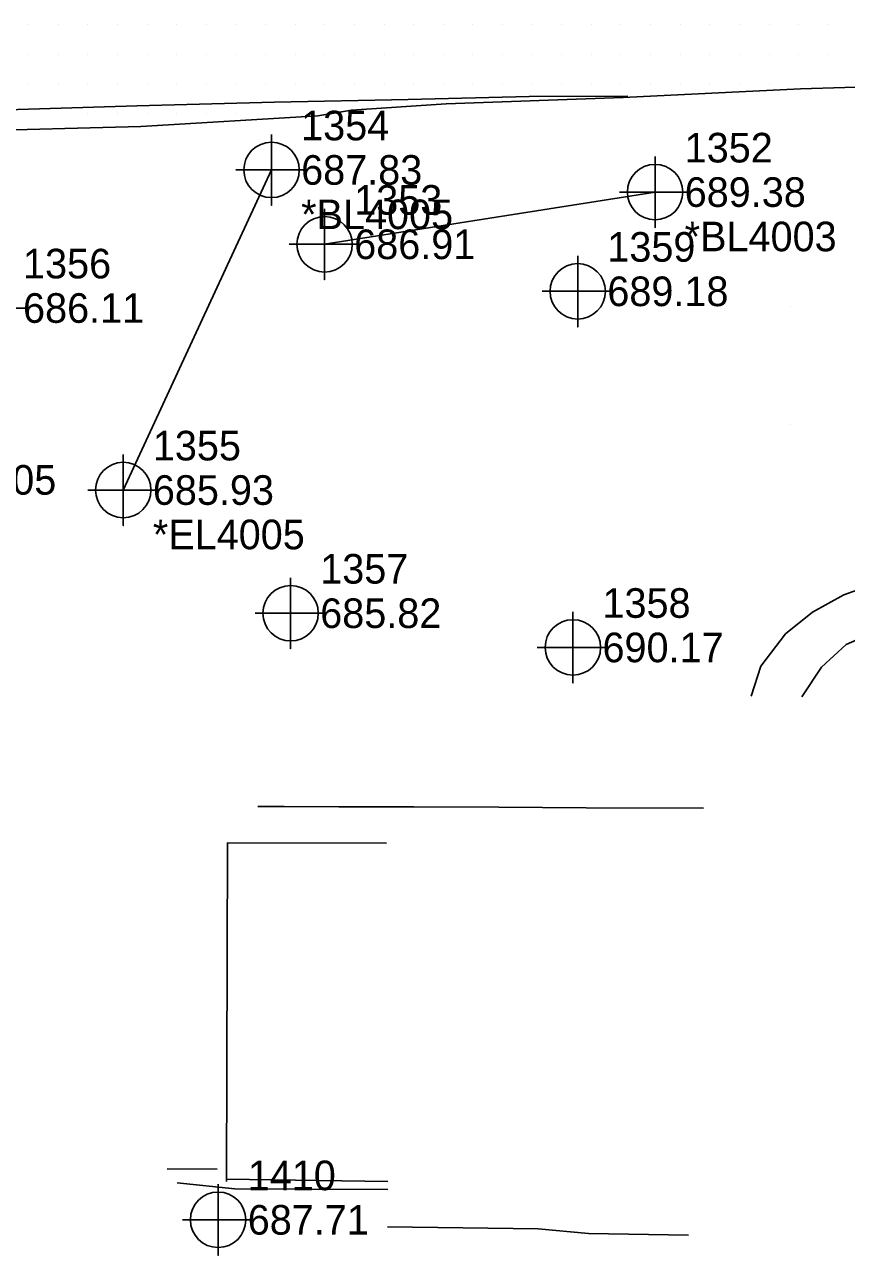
# Model space of a CAD drawing. Extents: x 1755643 to 1760494, y 736519 to 737621.
# Drawn here: x 1759120.9 to 1759190.3, y 736914.8 to 737018.8 of the extents above; entities that cross this region are included whole.
import ezdxf

# ---------------------------------------------------------------- set-up
doc = ezdxf.new("R2010")
doc.units = 0
for name, color, linetype in [('Exist Horizontal Alignment Curve and Spiral Data', 7, 'Continuous'), ('Exist Horizontal Alignment Direction Label', 7, 'Continuous'), ('Exist Railroads Standard Gauge', 7, 'Continuous'), ('Exist Roads EOT', 7, 'Continuous'), ('Old_Level_1', 7, 'Continuous'), ('Old_Level_10', 7, 'Continuous'), ('Old_Level_2', 7, 'Continuous'), ('Old_Level_3', 7, 'Continuous'), ('Prop Corridor Linear Feature', 7, 'Continuous'), ('Prop Dimension', 7, 'Continuous'), ('Prop EOT Dash', 7, 'Continuous'), ('Prop Horizontal Alignment Direction Label', 7, 'Continuous'), ('Prop Lane Lines', 7, 'Continuous'), ('Prop Paint Stripe', 7, 'Continuous'), ('Prop Paved Shoulder', 7, 'Continuous'), ('Scratch_Level_1', 7, 'Continuous'), ('Scratch_Level_2', 7, 'Continuous'), ('Scratch_Level_5', 7, 'Continuous'), ('Scratch_Level_9', 7, 'Continuous')]:
    doc.layers.add(name, color=color, linetype=linetype)

msp = doc.modelspace()

# ---------------------------------------------------------------- linework, layer by layer
at = {"layer": 'Exist Horizontal Alignment Curve and Spiral Data'}
for points in [[(1759167.6, 736999.23), (1759167.6, 736993.23), (1759167.6, 736996.23), (1759170.6, 736996.23), (1759164.6, 736996.23)], [(1759118.27, 736997.82), (1759118.27, 736991.82), (1759118.27, 736994.82), (1759121.27, 736994.82), (1759115.27, 736994.82)], [(1759143.36, 736972.05), (1759143.36, 736966.05), (1759143.36, 736969.05), (1759146.36, 736969.05), (1759140.36, 736969.05)], [(1759167.19, 736969.16), (1759167.19, 736963.16), (1759167.19, 736966.16), (1759170.19, 736966.16), (1759164.19, 736966.16)], [(1759137.24, 736920.83), (1759137.24, 736914.83), (1759137.24, 736917.83), (1759140.24, 736917.83), (1759134.24, 736917.83)]]:
    msp.add_lwpolyline(points, dxfattribs=at)
for centre in [(1759167.6, 736996.23), (1759143.36, 736969.05), (1759167.19, 736966.16), (1759137.24, 736917.83)]:
    msp.add_circle(centre, 2.34, dxfattribs=at)
at = {"layer": 'Exist Railroads Standard Gauge'}
for p, q in [((1759137.16, 736922.12), (1759132.93, 736922.13)), ((1759137.94, 736921.25), (1759151.58, 736921.07))]:
    msp.add_line(p, q, dxfattribs=at)
for points in [[(1759182.25, 736962.05), (1759183.06, 736964.58), (1759185.15, 736967.32), (1759187.42, 736969.13), (1759190.07, 736970.61), (1759194.08, 736972.04), (1759207.32, 736975.19)], [(1759207.32, 736975.19), (1759207.3, 736971.15), (1759199.22, 736969.52), (1759193.82, 736967.96), (1759190.26, 736966.41), (1759188.17, 736964.49), (1759186.53, 736962)], [(1759178.22, 736952.6), (1759168.31, 736952.63), (1759160.94, 736952.66), (1759153.75, 736952.69), (1759147.42, 736952.71), (1759142.82, 736952.72), (1759140.58, 736952.73)], [(1759151.45, 736949.63), (1759138.04, 736949.67), (1759137.94, 736921.25), (1759137.94, 736921.07)], [(1759151.58, 736920.4), (1759138.64, 736920.45), (1759133.78, 736920.95)], [(1759151.54, 736917.24), (1759164.26, 736917.07), (1759168.5, 736916.66), (1759176.94, 736916.53)]]:
    msp.add_lwpolyline(points, dxfattribs=at)
at = {"layer": 'Old_Level_10'}
for points in [[(1759174.13, 737007.61), (1759174.13, 737001.61), (1759174.13, 737004.61), (1759177.13, 737004.61), (1759171.13, 737004.61)], [(1759146.23, 737003.2), (1759146.23, 736997.2), (1759146.23, 737000.2), (1759149.23, 737000.2), (1759143.23, 737000.2)]]:
    msp.add_lwpolyline(points, dxfattribs=at)
for centre in [(1759174.13, 737004.61), (1759146.23, 737000.2)]:
    msp.add_circle(centre, 2.34, dxfattribs=at)
at = {"layer": 'Prop Corridor Linear Feature'}
msp.add_lwpolyline([(1759145.67, 737011.05), (1759130.72, 737010.15), (1759115.74, 737009.75), (1759112.46, 737010.95), (1759107.45, 737010.81)], dxfattribs=at)
at = {"layer": 'Prop Dimension'}
msp.add_line((1759174.13, 737004.61), (1759146.23, 737000.2), dxfattribs=at)
at = {"layer": 'Prop Lane Lines'}
for points in [[(1759141.75, 737009.48), (1759141.75, 737003.48), (1759141.75, 737006.48), (1759144.75, 737006.48), (1759138.75, 737006.48)], [(1759129.23, 736982.45), (1759129.23, 736976.45), (1759129.23, 736979.45), (1759132.23, 736979.45), (1759126.23, 736979.45)]]:
    msp.add_lwpolyline(points, dxfattribs=at)
for centre in [(1759141.75, 737006.48), (1759129.23, 736979.45)]:
    msp.add_circle(centre, 2.34, dxfattribs=at)
at = {"layer": 'Prop Paint Stripe'}
for p, q in [((1759185.53, 736994.98), (1759185.53, 736994.98)), ((1759185.53, 736984.98), (1759185.53, 736984.98))]:
    msp.add_line(p, q, dxfattribs=at)
at = {"layer": 'Scratch_Level_1'}
msp.add_lwpolyline([(1759206.09, 737011.82), (1759204.75, 737012.52), (1759202.7, 737013.24), (1759201.37, 737013.77), (1759186.4, 737013.34), (1759171.45, 737012.59), (1759156.49, 737012.06), (1759148.5, 737011.53), (1759145.67, 737011.05)], dxfattribs=at)
at = {"layer": 'Scratch_Level_2'}
for p, q in [((1759121.25, 737018.75), (1759121.25, 737018.75)), ((1759123.75, 737018.75), (1759123.75, 737018.75)), ((1759126.25, 737018.75), (1759126.25, 737018.75)), ((1759128.75, 737018.75), (1759128.75, 737018.75)), ((1759131.25, 737018.75), (1759131.25, 737018.75)), ((1759133.75, 737018.75), (1759133.75, 737018.75)), ((1759136.25, 737018.75), (1759136.25, 737018.75)), ((1759138.75, 737018.75), (1759138.75, 737018.75)), ((1759141.25, 737018.75), (1759141.25, 737018.75)), ((1759143.75, 737018.75), (1759143.75, 737018.75)), ((1759146.25, 737018.75), (1759146.25, 737018.75)), ((1759148.75, 737018.75), (1759148.75, 737018.75)), ((1759151.25, 737018.75), (1759151.25, 737018.75)), ((1759153.75, 737018.75), (1759153.75, 737018.75)), ((1759156.25, 737018.75), (1759156.25, 737018.75)), ((1759158.75, 737018.75), (1759158.75, 737018.75)), ((1759161.25, 737018.75), (1759161.25, 737018.75)), ((1759163.75, 737018.75), (1759163.75, 737018.75)), ((1759166.25, 737018.75), (1759166.25, 737018.75)), ((1759168.75, 737018.75), (1759168.75, 737018.75)), ((1759171.25, 737018.75), (1759171.25, 737018.75)), ((1759173.75, 737018.75), (1759173.75, 737018.75)), ((1759176.25, 737018.75), (1759176.25, 737018.75)), ((1759178.75, 737018.75), (1759178.75, 737018.75)), ((1759181.25, 737018.75), (1759181.25, 737018.75)), ((1759183.75, 737018.75), (1759183.75, 737018.75)), ((1759186.25, 737018.75), (1759186.25, 737018.75)), ((1759188.75, 737018.75), (1759188.75, 737018.75)), ((1759121.25, 737016.25), (1759121.25, 737016.25)), ((1759123.75, 737016.25), (1759123.75, 737016.25)), ((1759126.25, 737016.25), (1759126.25, 737016.25)), ((1759128.75, 737016.25), (1759128.75, 737016.25)), ((1759131.25, 737016.25), (1759131.25, 737016.25)), ((1759133.75, 737016.25), (1759133.75, 737016.25)), ((1759136.25, 737016.25), (1759136.25, 737016.25)), ((1759138.75, 737016.25), (1759138.75, 737016.25)), ((1759141.25, 737016.25), (1759141.25, 737016.25)), ((1759143.75, 737016.25), (1759143.75, 737016.25)), ((1759146.25, 737016.25), (1759146.25, 737016.25)), ((1759148.75, 737016.25), (1759148.75, 737016.25)), ((1759151.25, 737016.25), (1759151.25, 737016.25)), ((1759153.75, 737016.25), (1759153.75, 737016.25)), ((1759156.25, 737016.25), (1759156.25, 737016.25)), ((1759158.75, 737016.25), (1759158.75, 737016.25)), ((1759161.25, 737016.25), (1759161.25, 737016.25)), ((1759163.75, 737016.25), (1759163.75, 737016.25)), ((1759166.25, 737016.25), (1759166.25, 737016.25)), ((1759168.75, 737016.25), (1759168.75, 737016.25)), ((1759171.25, 737016.25), (1759171.25, 737016.25)), ((1759173.75, 737016.25), (1759173.75, 737016.25)), ((1759176.25, 737016.25), (1759176.25, 737016.25)), ((1759178.75, 737016.25), (1759178.75, 737016.25)), ((1759181.25, 737016.25), (1759181.25, 737016.25)), ((1759183.75, 737016.25), (1759183.75, 737016.25)), ((1759186.25, 737016.25), (1759186.25, 737016.25)), ((1759188.75, 737016.25), (1759188.75, 737016.25)), ((1759121.25, 737013.75), (1759121.25, 737013.75)), ((1759123.75, 737013.75), (1759123.75, 737013.75)), ((1759126.25, 737013.75), (1759126.25, 737013.75)), ((1759128.75, 737013.75), (1759128.75, 737013.75)), ((1759131.25, 737013.75), (1759131.25, 737013.75)), ((1759133.75, 737013.75), (1759133.75, 737013.75)), ((1759136.25, 737013.75), (1759136.25, 737013.75)), ((1759138.75, 737013.75), (1759138.75, 737013.75)), ((1759141.25, 737013.75), (1759141.25, 737013.75)), ((1759143.75, 737013.75), (1759143.75, 737013.75)), ((1759146.25, 737013.75), (1759146.25, 737013.75)), ((1759148.75, 737013.75), (1759148.75, 737013.75)), ((1759151.25, 737013.75), (1759151.25, 737013.75)), ((1759153.75, 737013.75), (1759153.75, 737013.75)), ((1759156.25, 737013.75), (1759156.25, 737013.75)), ((1759158.75, 737013.75), (1759158.75, 737013.75)), ((1759161.25, 737013.75), (1759161.25, 737013.75)), ((1759163.75, 737013.75), (1759163.75, 737013.75)), ((1759166.25, 737013.75), (1759166.25, 737013.75)), ((1759168.75, 737013.75), (1759168.75, 737013.75)), ((1759171.25, 737013.75), (1759171.25, 737013.75)), ((1759173.75, 737013.75), (1759173.75, 737013.75)), ((1759176.25, 737013.75), (1759176.25, 737013.75)), ((1759178.75, 737013.75), (1759178.75, 737013.75)), ((1759181.25, 737013.75), (1759181.25, 737013.75)), ((1759183.75, 737013.75), (1759183.75, 737013.75)), ((1759126.25, 737011.25), (1759126.25, 737011.25)), ((1759128.75, 737011.25), (1759128.75, 737011.25)), ((1759131.25, 737011.25), (1759131.25, 737011.25)), ((1759133.75, 737011.25), (1759133.75, 737011.25)), ((1759136.25, 737011.25), (1759136.25, 737011.25)), ((1759138.75, 737011.25), (1759138.75, 737011.25))]:
    msp.add_line(p, q, dxfattribs=at)
at = {"layer": 'Scratch_Level_5'}
msp.add_lwpolyline([(1759171.82, 737012.72), (1759163.49, 737012.68), (1759153.29, 737012.42), (1759142, 737012.2), (1759130.39, 737011.89), (1759118.48, 737011.54), (1759108.2, 737011.22), (1759095.54, 737010.79), (1759083.43, 737010.44), (1759069.08, 737010.03)], dxfattribs=at)
at = {"layer": 'Scratch_Level_9'}
msp.add_line((1759141.75, 737006.48), (1759129.23, 736979.45), dxfattribs=at)

# ---------------------------------------------------------------- texts
at = {"layer": 'Exist Horizontal Alignment Direction Label'}
for s, p in [('*BL4005', (1759144.25, 737001.48)), ('*BL4005', (1759110.75, 736979.06)), ('*EL4005', (1759131.73, 736974.45))]:
    msp.add_text(s, height=2.5, dxfattribs=at).set_placement(p)
at = {"layer": 'Exist Roads EOT'}
for s, p in [('1359', (1759170.1, 736998.73)), ('1356', (1759120.77, 736997.32)), ('1357', (1759145.86, 736971.55)), ('1358', (1759169.69, 736968.66)), ('1410', (1759139.74, 736920.33))]:
    msp.add_text(s, height=2.5, dxfattribs=at).set_placement(p)
at = {"layer": 'Old_Level_1'}
for s, p in [('1352', (1759176.63, 737007.11)), ('1353', (1759148.73, 737002.7))]:
    msp.add_text(s, height=2.5, dxfattribs=at).set_placement(p)
at = {"layer": 'Old_Level_2'}
for s, p in [('689.38', (1759176.63, 737003.36)), ('686.91', (1759148.73, 736998.95))]:
    msp.add_text(s, height=2.5, dxfattribs=at).set_placement(p)
at = {"layer": 'Old_Level_3'}
for s, p in [('687.83', (1759144.25, 737005.23)), ('685.93', (1759131.73, 736978.2))]:
    msp.add_text(s, height=2.5, dxfattribs=at).set_placement(p)
at = {"layer": 'Prop EOT Dash'}
for s, p in [('1354', (1759144.25, 737008.98)), ('1355', (1759131.73, 736981.95))]:
    msp.add_text(s, height=2.5, dxfattribs=at).set_placement(p)
at = {"layer": 'Prop Horizontal Alignment Direction Label'}
msp.add_text('*BL4003', height=2.5, dxfattribs=at).set_placement((1759176.63, 736999.61))
at = {"layer": 'Prop Paved Shoulder'}
for s, p in [('689.18', (1759170.1, 736994.98)), ('686.11', (1759120.77, 736993.57)), ('685.82', (1759145.86, 736967.8)), ('690.17', (1759169.69, 736964.91)), ('687.71', (1759139.74, 736916.58))]:
    msp.add_text(s, height=2.5, dxfattribs=at).set_placement(p)

doc.saveas('drawing.dxf')
